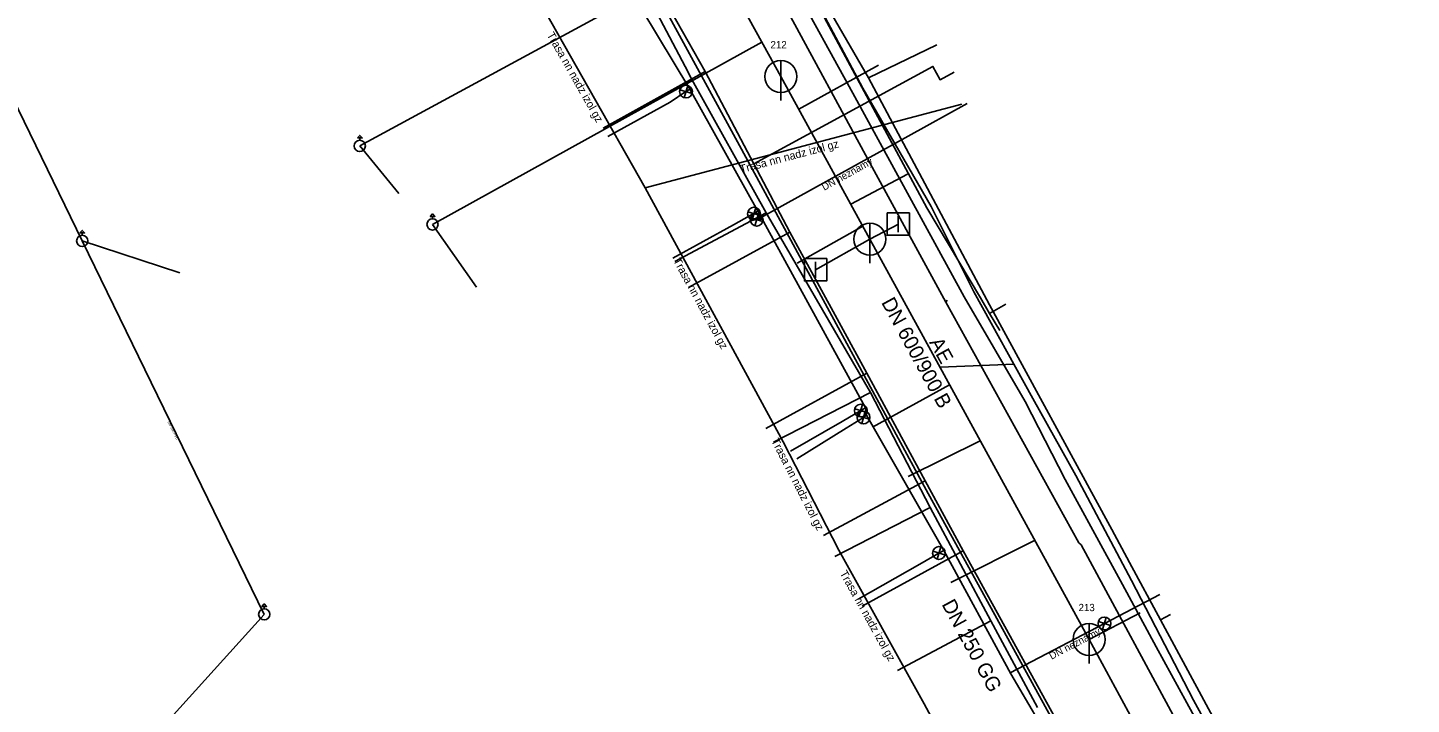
# Model space of a CAD drawing. Extents: x -493753 to -49291, y -1127285 to -112662.
# Drawn here: x -492942.9 to -492856.4, y -1126736.7 to -1126694.5 of the extents above; entities that cross this region are included whole.
import ezdxf

# ---------------------------------------------------------------- set-up
doc = ezdxf.new("R2010")
doc.units = 0
for name, color, linetype in [('Vrstva 1', 7, 'Continuous'), ('Vrstva 11', 7, 'Continuous'), ('Vrstva 15', 7, 'Continuous'), ('Vrstva 17', 7, 'Continuous'), ('Vrstva 19', 7, 'Continuous'), ('Vrstva 20', 7, 'Continuous'), ('Vrstva 22', 7, 'Continuous'), ('Vrstva 24', 7, 'Continuous'), ('Vrstva 26', 7, 'Continuous'), ('Vrstva 39', 7, 'Continuous'), ('Vrstva 5', 7, 'Continuous'), ('Vrstva 6', 7, 'Continuous'), ('Vrstva 9', 7, 'Continuous')]:
    doc.layers.add(name, color=color, linetype=linetype)

# ---------------------------------------------------------------- blocks, each defined once
blk = doc.blocks.new('_UZAV0')
at = {"layer": 'Vrstva 1'}
for p, q in [((-0.035, -0.035), (0.035, 0.035)), ((0.035, -0.035), (-0.035, 0.035))]:
    blk.add_line(p, q, dxfattribs=at)
for radius in [0.05, 0.0025]:
    blk.add_circle((0, 0), radius, dxfattribs=at)
blk = doc.blocks.new('_VPUST')
at = {"layer": 'Vrstva 1'}
blk.add_line((0, 0.025), (0, -0.025), dxfattribs=at)
blk.add_lwpolyline([(-0.035, 0.035), (0.035, 0.035), (0.035, -0.035), (-0.035, -0.035), (-0.035, 0.035)], dxfattribs=at)
blk = doc.blocks.new('_SACHT')
at = {"layer": 'Vrstva 1'}
blk.add_line((0, 0.035), (0, 0.05), dxfattribs=at)
blk.add_lwpolyline([(-0.015, 0.05), (0, 0.065), (0.015, 0.05), (0.0025, 0.05)], close=True, dxfattribs=at)
blk.add_circle((0, 0), 0.035, dxfattribs=at)
blk = doc.blocks.new('_SACH0')
at = {"layer": 'Vrstva 1'}
blk.add_line((0, 0.05), (0, -0.075), dxfattribs=at)
blk.add_circle((0, 0), 0.05, dxfattribs=at)

msp = doc.modelspace()

# ---------------------------------------------------------------- linework, layer by layer
at = {"layer": 'Vrstva 1'}
for p, q in [((-492906.92, -1126700.77), (-492900.54, -1126697.23)), ((-492895.26, -1126707.27), (-492901.58, -1126710.72)), ((-492882.78, -1126712.34), (-492881.78, -1126711.75)), ((-492890.45, -1126716.07), (-492896.76, -1126719.52)), ((-492886.81, -1126722.78), (-492893.15, -1126726.2)), ((-492884.43, -1126727.16), (-492890.75, -1126730.61))]:
    msp.add_line(p, q, dxfattribs=at)
for points in [[(-492933.75, -1126611.37), (-492936.63, -1126613.76), (-492929.27, -1126628.23), (-492921.07, -1126642.52), (-492915.19, -1126653.05), (-492909.09, -1126664.67), (-492905.55, -1126670.97), (-492900.94, -1126679.32), (-492893.67, -1126692.81), (-492886.7, -1126705.75), (-492883.36, -1126711.37), (-492882.78, -1126712.34), (-492882.15, -1126713.4)], [(-492937.42, -1126630.24), (-492931.64, -1126641.3), (-492927.73, -1126648.23), (-492923.99, -1126654.85), (-492920.54, -1126661.22), (-492918.14, -1126665.44), (-492916.71, -1126668.03), (-492912.53, -1126675.61), (-492909.26, -1126681.56), (-492909.12, -1126681.82), (-492904.44, -1126690.35), (-492900.54, -1126697.23), (-492897.51, -1126702.99), (-492895.26, -1126707.27), (-492890.45, -1126716.07), (-492886.81, -1126722.78), (-492884.43, -1126727.16), (-492878.44, -1126738.04), (-492875.73, -1126742.95)], [(-492885, -1126697.27), (-492885.88, -1126697.75), (-492886.32, -1126696.92), (-492897.51, -1126702.99)]]:
    msp.add_lwpolyline(points, dxfattribs=at)
at = {"layer": 'Vrstva 11'}
msp.add_lwpolyline([(-492848.73, -1126797.53), (-492854.56, -1126788.15), (-492854.38, -1126786.02), (-492853.2, -1126784.39), (-492859.9, -1126772.1), (-492871.87, -1126750.4), (-492886.74, -1126723.34), (-492898.4, -1126701.86), (-492908, -1126684.26), (-492916.54, -1126668.65), (-492921.45, -1126660.08), (-492926.55, -1126650.44), (-492932.03, -1126640.6), (-492935.8, -1126632.89)], dxfattribs=at)
at = {"layer": 'Vrstva 15'}
for p, q in [((-492895.82, -1126697.55), (-492919.1, -1126655.44)), ((-492922.12, -1126701.88), (-492900.04, -1126689.91)), ((-492917.58, -1126706.78), (-492897, -1126695.41)), ((-492889.72, -1126696.85), (-492894.7, -1126699.58)), ((-492890.26, -1126707.7), (-492895.82, -1126697.55)), ((-492919.68, -1126704.86), (-492922.12, -1126701.88)), ((-492887.91, -1126703.65), (-492891.45, -1126705.52)), ((-492914.84, -1126710.7), (-492917.58, -1126706.78)), ((-492894.81, -1126709.2), (-492890.7, -1126706.89)), ((-492888.48, -1126706.76), (-492890.26, -1126707.7)), ((-492928.09, -1126731.12), (-492939.46, -1126707.81)), ((-492933.36, -1126709.8), (-492939.46, -1126707.81)), ((-492893.65, -1126709.61), (-492890.26, -1126707.7)), ((-492876.57, -1126732.69), (-492890.26, -1126707.7)), ((-492881.24, -1126715.5), (-492885.88, -1126715.7)), ((-492890.1, -1126719.44), (-492885.28, -1126716.8)), ((-492887.86, -1126722.52), (-492883.37, -1126720.29)), ((-492885.2, -1126729.13), (-492879.97, -1126726.5)), ((-492935.54, -1126739.36), (-492928.09, -1126731.12)), ((-492873.38, -1126731.02), (-492876.57, -1126732.69)), ((-492855.18, -1126772.05), (-492876.57, -1126732.69))]:
    msp.add_line(p, q, dxfattribs=at)
msp.add_lwpolyline([(-492939.46, -1126707.81), (-492946.73, -1126692.9), (-492958.46, -1126670.96)], dxfattribs=at)
at = {"layer": 'Vrstva 20'}
for p, q in [((-492906.63, -1126701.3), (-492902.73, -1126699.14)), ((-492884.19, -1126699.24), (-492887.87, -1126701.27)), ((-492898.78, -1126706.8), (-492897.26, -1126705.96)), ((-492902.56, -1126708.88), (-492898.78, -1126706.8)), ((-492895.22, -1126720.93), (-492892, -1126719.08)), ((-492894.83, -1126721.41), (-492891.75, -1126719.5)), ((-492890.99, -1126730.17), (-492887.15, -1126727.98))]:
    msp.add_line(p, q, dxfattribs=at)
for points in [[(-492852.32, -1126789.23), (-492857.95, -1126778.05), (-492862.82, -1126769.39), (-492866.35, -1126762.51), (-492876.86, -1126743.48), (-492879.77, -1126737.71), (-492881.46, -1126734.83), (-492885.64, -1126727.14), (-492890.48, -1126718.68), (-492890.54, -1126718.22), (-492897.26, -1126705.96), (-492901.5, -1126698.34), (-492906.52, -1126690), (-492906.82, -1126689.41), (-492911.08, -1126681.1), (-492913.41, -1126677.49)], [(-492902.73, -1126699.14), (-492901.75, -1126698.49), (-492901.5, -1126698.34)], [(-492887.87, -1126701.27), (-492897.33, -1126706.49), (-492896.98, -1126706.46)], [(-492892, -1126719.08), (-492890.83, -1126718.4), (-492890.54, -1126718.22)], [(-492891.75, -1126719.5), (-492890.66, -1126718.83), (-492890.48, -1126718.68)], [(-492887.15, -1126727.98), (-492885.95, -1126727.29), (-492885.64, -1126727.14)], [(-492872.15, -1126729.87), (-492875.61, -1126731.69), (-492881.5, -1126734.76)]]:
    msp.add_lwpolyline(points, dxfattribs=at)
at = {"layer": 'Vrstva 26'}
for p, q in [((-492889.99, -1126703.43), (-492901.81, -1126681.63)), ((-492885.51, -1126711.64), (-492889.99, -1126703.43)), ((-492885.44, -1126711.51), (-492885.51, -1126711.64)), ((-492877.22, -1126726.66), (-492885.51, -1126711.64)), ((-492877.22, -1126726.66), (-492877.07, -1126726.79)), ((-492869.14, -1126741.41), (-492877.07, -1126726.79))]:
    msp.add_line(p, q, dxfattribs=at)
at = {"layer": 'Vrstva 39'}
for points in [[(-492901.42, -1126678.49), (-492890.35, -1126697.64)], [(-492904.9, -1126691.03), (-492901.8, -1126696.93)], [(-492890.35, -1126697.64), (-492886.07, -1126695.57)], [(-492901.8, -1126696.93), (-492901.38, -1126697.73)], [(-492901.38, -1126697.73), (-492906.88, -1126700.85)], [(-492901.38, -1126697.73), (-492896.73, -1126706.06)], [(-492874.04, -1126727.89), (-492875.15, -1126725.83), (-492882.8, -1126711.81), (-492890.35, -1126697.64)], [(-492896.73, -1126706.06), (-492902.44, -1126709.09)], [(-492896.73, -1126706.06), (-492890.23, -1126717.27)], [(-492890.23, -1126717.27), (-492896.29, -1126720.38)], [(-492886.5, -1126724.46), (-492890.23, -1126717.27)], [(-492886.5, -1126724.46), (-492892.44, -1126727.5)], [(-492886.5, -1126724.46), (-492882.71, -1126731.53)], [(-492872.11, -1126731.46), (-492874.04, -1126727.89)], [(-492888.53, -1126734.62), (-492882.71, -1126731.53)], [(-492879.8, -1126736.94), (-492882.71, -1126731.53)], [(-492871.48, -1126731.13), (-492872.11, -1126731.46)], [(-492872.11, -1126731.46), (-492856.16, -1126761), (-492845.35, -1126780.67), (-492844.99, -1126780.49)]]:
    msp.add_lwpolyline(points, dxfattribs=at)
at = {"layer": 'Vrstva 5'}
for points in [[(-492930.18, -1126627.53), (-492929.7, -1126628.3), (-492927.22, -1126633.26), (-492923.26, -1126640.65), (-492921.49, -1126643.52), (-492920.82, -1126643.97), (-492919.81, -1126645.85), (-492919.15, -1126647.03), (-492919.14, -1126647.42), (-492915.28, -1126654.98), (-492910.97, -1126662.52), (-492907.05, -1126669.53), (-492905.34, -1126672.14), (-492902.08, -1126678.46), (-492899.06, -1126684.17), (-492895.14, -1126691.66), (-492891.32, -1126698.58), (-492884.38, -1126711.3), (-492880.56, -1126717.84), (-492878.06, -1126722.71), (-492874.49, -1126729.25), (-492872.37, -1126733.14)], [(-492911.33, -1126692.08), (-492904.3, -1126704.49)], [(-492884.52, -1126699.27), (-492904.3, -1126704.49)], [(-492904.3, -1126704.49), (-492895.67, -1126720.35)], [(-492895.67, -1126720.35), (-492892.21, -1126727.11)], [(-492892.21, -1126727.11), (-492886.87, -1126736.71)], [(-492872.37, -1126733.14), (-492870.46, -1126736.65), (-492865.7, -1126745.32), (-492862.28, -1126751.7), (-492860.81, -1126754.35), (-492859.38, -1126754.54), (-492856.69, -1126753.45)], [(-492886.87, -1126736.71), (-492882.91, -1126744.04)]]:
    msp.add_lwpolyline(points, dxfattribs=at)
at = {"layer": 'Vrstva 6'}
msp.add_lwpolyline([(-492927.01, -1126633.18), (-492921.98, -1126642.45), (-492921.27, -1126643.29), (-492920.62, -1126643.94), (-492919.69, -1126645.86), (-492919.21, -1126647.18), (-492918.59, -1126648.02), (-492914.95, -1126654.92), (-492910.66, -1126662.41), (-492906.73, -1126669.35), (-492905.2, -1126672), (-492901.68, -1126678.27), (-492898.39, -1126683.83), (-492894.4, -1126691.31), (-492890.71, -1126698.27), (-492886.43, -1126705.66), (-492883.76, -1126710.99), (-492880.09, -1126717.64), (-492877.39, -1126722.45), (-492873.92, -1126729.01), (-492870.04, -1126736.47), (-492865.33, -1126745.11)], dxfattribs=at)

# ---------------------------------------------------------------- block references
at = {"layer": 'Vrstva 17'}
for name, p, xscale, yscale in [('_SACH0', (-492895.82, -1126697.55), 19.997500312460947, 19.997500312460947), ('_SACHT', (-492922.12, -1126701.88), 9.998750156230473, 9.998750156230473), ('_SACHT', (-492917.58, -1126706.78), 9.998750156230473, 9.998750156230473), ('_VPUST', (-492888.49, -1126706.76), 19.997500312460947, 19.997500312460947), ('_SACHT', (-492939.46, -1126707.81), 9.998750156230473, 9.998750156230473), ('_SACH0', (-492890.26, -1126707.7), 19.997500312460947, 19.997500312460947), ('_VPUST', (-492893.65, -1126709.61), 19.997500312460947, 19.997500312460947), ('_SACHT', (-492928.09, -1126731.12), 9.998750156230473, 9.998750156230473), ('_SACH0', (-492876.57, -1126732.69), 19.997500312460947, 19.997500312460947)]:
    msp.add_blockref(name, p, dxfattribs=dict(at, xscale=xscale, yscale=yscale))
at = {"layer": 'Vrstva 22'}
for p, xscale, yscale, rotation in [((-492901.75, -1126698.49), 7.999000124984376, 7.999000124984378, -61.250922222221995), ((-492897.5, -1126706.11), 7.999000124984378, 7.999000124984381, -61.96957222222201), ((-492897.33, -1126706.49), 7.999000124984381, 7.99900012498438, 118.414777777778), ((-492890.83, -1126718.4), 7.999000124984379, 7.999000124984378, 28.542533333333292), ((-492890.66, -1126718.83), 7.999000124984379, 7.999000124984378, 28.542533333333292), ((-492885.95, -1126727.29), 7.999000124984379, 7.999000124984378, 28.542533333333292), ((-492875.61, -1126731.69), 7.999000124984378, 7.999000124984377, -61.99343055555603)]:
    msp.add_blockref('_UZAV0', p, dxfattribs=dict(at, xscale=xscale, yscale=yscale, rotation=rotation))

# ---------------------------------------------------------------- texts
at = {"layer": 'Vrstva 19'}
for s, p in [('212', (-492896.469, -1126695.79)), ('213', (-492877.229, -1126730.92))]:
    msp.add_text(s, height=0.4549, dxfattribs=at).set_placement(p)
for s, height, rotation, p in [('DN 600/900 B', 0.90989, 298.70829, (-492889.571, -1126711.647)), ('AE', 0.9099, 298.70829, (-492886.578, -1126714.137)), ('DN 150 PVC', 0.1605, 295.99338, (-492934.133, -1126719.105))]:
    msp.add_text(s, height=height, rotation=rotation, dxfattribs=at).set_placement(p)
at = {"layer": 'Vrstva 24'}
for s, height, rotation, p in [('DN neznámý', 0.455, 28.88297, (-492893.114, -1126704.687)), ('DN 250 GG', 0.9099, 298.5309, (-492885.802, -1126730.488)), ('DN neznámý', 0.455, 27.53788, (-492878.917, -1126733.958))]:
    msp.add_text(s, height=height, rotation=rotation, dxfattribs=at).set_placement(p)
at = {"layer": 'Vrstva 9'}
for rotation, p in [(299.53808, (-492910.453, -1126694.947)), (14.78345, (-492898.309, -1126703.585)), (298.54385, (-492902.563, -1126709.038)), (297.10644, (-492896.435, -1126720.285)), (299.08437, (-492892.156, -1126728.549))]:
    msp.add_text('Trasa nn nadz izol gz', height=0.5, rotation=rotation, dxfattribs=at).set_placement(p)

doc.saveas('drawing.dxf')
